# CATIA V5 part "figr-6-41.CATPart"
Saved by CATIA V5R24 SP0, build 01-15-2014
Part number: Part1
Bounding box of the stored display mesh (mm): x 0 to 45, y 0 to 76.536, z 0 to 111.001
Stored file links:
  D:\KAVITA\CATIA V5-6R2014 Project_ Kavita\CATIA V5-6R2014_partfiles\Partfiles\c06_catia_v5-6r2014_prt\figr-6-41.CATPart
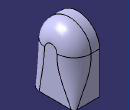
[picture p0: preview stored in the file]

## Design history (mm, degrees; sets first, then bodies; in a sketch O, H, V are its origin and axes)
Body1 (main body)
  Sketch1 on yz-plane, origin (0, 0, 0), H (0, 1, 0), V (0, 0, 1)
    line L1 (0, 0) -> (76.5361, 0)
    line L2 (76.5361, 0) -> (76.5361, 72.7325)
    line L3 (0, 0) -> (0, 72.7325)
    arc A1 centre (38.2681, 72.7325) radius 38.2681 from (76.5361, 72.7325) to (0, 72.7325) ccw
    horizontal: L1 H
    vertical: L2 V, L3 V
    tangency: A1 L3, A1 L2
  Pad1: profile Sketch1, direction (1, 0, 0), length 45
  Fillet1: on edge [face of Pad1 | face of Pad1] (x3)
